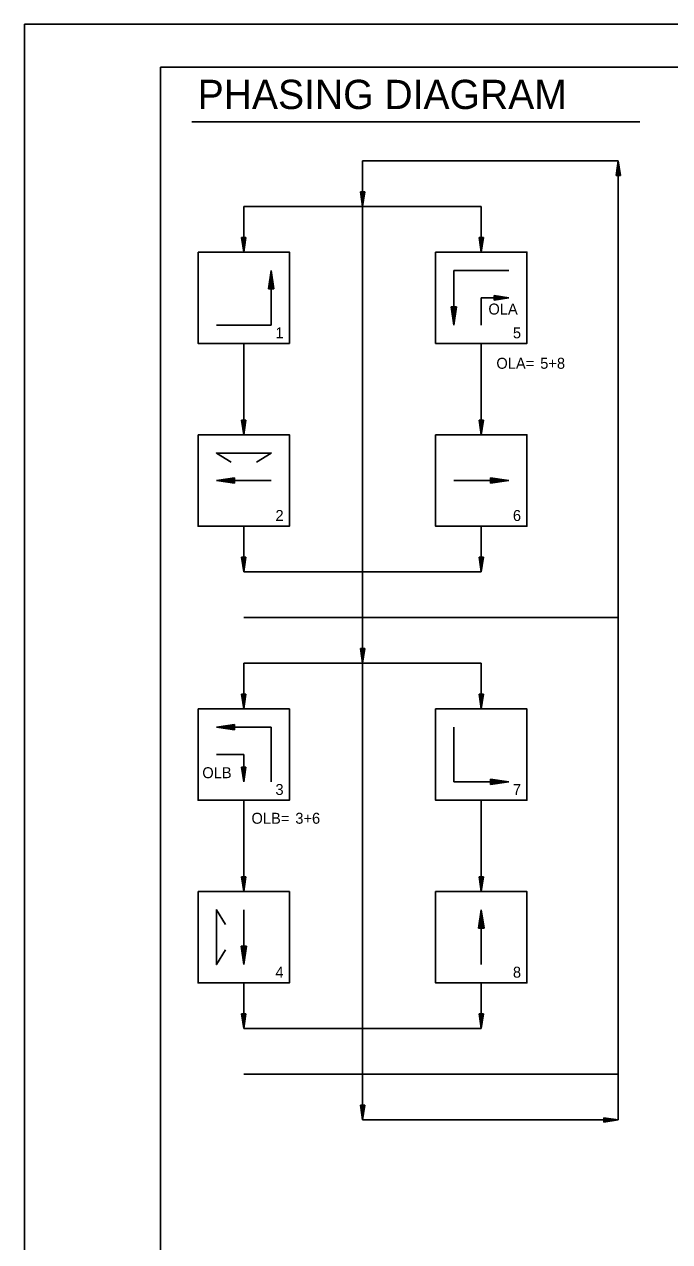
# Model space of a CAD drawing. Extents: x 659404 to 660404, y 642315 to 642955.
# Drawn here: x 659403.7 to 659580.3, y 642622 to 642955.1 of the extents above; entities that cross this region are included whole.
import ezdxf

# ---------------------------------------------------------------- set-up
doc = ezdxf.new("R2010")
doc.units = 0
for name, color, linetype in [('R_Border', 7, 'Continuous'), ('R_Draft', 7, 'Continuous'), ('R_No Plot', 7, 'Continuous'), ('T_Drafting', 7, 'Continuous'), ('T_Notes', 7, 'Continuous')]:
    doc.layers.add(name, color=color, linetype=linetype)

msp = doc.modelspace()

# ---------------------------------------------------------------- linework, layer by layer
at = {"layer": 'R_Border'}
for p, q in [((659440.89, 642943.46), (660389.43, 642943.46)), ((659440.89, 642327.08), (659440.89, 642943.46))]:
    msp.add_line(p, q, dxfattribs=at)
at = {"layer": 'R_Draft'}
for p, q in [((659565.63, 642913.79), (659566.23, 642917.79)), ((659565.73, 642913.79), (659566.23, 642917.12)), ((659565.83, 642913.79), (659566.23, 642916.43)), ((659566.83, 642913.79), (659566.23, 642917.79)), ((659566.73, 642913.79), (659566.23, 642917.12)), ((659566.63, 642913.79), (659566.23, 642916.43)), ((659565.63, 642913.79), (659566.83, 642913.79)), ((659565.93, 642913.79), (659566.23, 642915.76)), ((659566.04, 642913.79), (659566.23, 642915.09)), ((659566.14, 642913.79), (659566.23, 642914.42)), ((659566.53, 642913.79), (659566.23, 642915.76)), ((659566.43, 642913.79), (659566.23, 642915.09)), ((659566.32, 642913.79), (659566.23, 642914.42)), ((659495.63, 642909.29), (659496.23, 642905.29)), ((659496.83, 642909.29), (659495.63, 642909.29)), ((659495.73, 642909.29), (659496.23, 642905.95)), ((659495.83, 642909.29), (659496.23, 642906.64)), ((659495.93, 642909.29), (659496.23, 642907.31)), ((659496.03, 642909.29), (659496.23, 642907.99)), ((659496.14, 642909.29), (659496.23, 642908.65)), ((659496.83, 642909.29), (659496.23, 642905.29)), ((659496.42, 642909.29), (659496.23, 642907.99)), ((659496.63, 642909.29), (659496.23, 642906.64)), ((659496.73, 642909.29), (659496.23, 642905.95)), ((659496.53, 642909.29), (659496.23, 642907.31)), ((659496.32, 642909.29), (659496.23, 642908.65)), ((659463.13, 642896.79), (659463.73, 642892.79)), ((659464.33, 642896.79), (659463.13, 642896.79)), ((659463.23, 642896.79), (659463.73, 642893.45)), ((659463.33, 642896.79), (659463.73, 642894.14)), ((659463.43, 642896.79), (659463.73, 642894.81)), ((659463.53, 642896.79), (659463.73, 642895.49)), ((659463.64, 642896.79), (659463.73, 642896.15)), ((659464.33, 642896.79), (659463.73, 642892.79)), ((659463.92, 642896.79), (659463.73, 642895.49)), ((659464.13, 642896.79), (659463.73, 642894.14)), ((659464.23, 642896.79), (659463.73, 642893.45)), ((659464.03, 642896.79), (659463.73, 642894.81)), ((659463.82, 642896.79), (659463.73, 642896.15)), ((659528.13, 642896.79), (659528.73, 642892.79)), ((659529.33, 642896.79), (659528.13, 642896.79)), ((659528.23, 642896.79), (659528.73, 642893.45)), ((659528.33, 642896.79), (659528.73, 642894.14)), ((659528.43, 642896.79), (659528.73, 642894.81)), ((659528.53, 642896.79), (659528.73, 642895.49)), ((659528.64, 642896.79), (659528.73, 642896.15)), ((659529.33, 642896.79), (659528.73, 642892.79)), ((659528.92, 642896.79), (659528.73, 642895.49)), ((659529.13, 642896.79), (659528.73, 642894.14)), ((659529.23, 642896.79), (659528.73, 642893.45)), ((659529.03, 642896.79), (659528.73, 642894.81)), ((659528.82, 642896.79), (659528.73, 642896.15)), ((659463.13, 642846.79), (659463.73, 642842.79)), ((659464.33, 642846.79), (659463.13, 642846.79)), ((659463.23, 642846.79), (659463.73, 642843.45)), ((659463.33, 642846.79), (659463.73, 642844.14)), ((659463.43, 642846.79), (659463.73, 642844.81)), ((659463.53, 642846.79), (659463.73, 642845.49)), ((659463.64, 642846.79), (659463.73, 642846.15)), ((659464.33, 642846.79), (659463.73, 642842.79)), ((659463.92, 642846.79), (659463.73, 642845.49)), ((659464.13, 642846.79), (659463.73, 642844.14)), ((659464.23, 642846.79), (659463.73, 642843.45)), ((659464.03, 642846.79), (659463.73, 642844.81)), ((659463.82, 642846.79), (659463.73, 642846.15)), ((659528.13, 642846.79), (659528.73, 642842.79)), ((659529.33, 642846.79), (659528.13, 642846.79)), ((659528.23, 642846.79), (659528.73, 642843.45)), ((659528.33, 642846.79), (659528.73, 642844.14)), ((659528.43, 642846.79), (659528.73, 642844.81)), ((659528.53, 642846.79), (659528.73, 642845.49)), ((659528.64, 642846.79), (659528.73, 642846.15)), ((659529.33, 642846.79), (659528.73, 642842.79)), ((659528.92, 642846.79), (659528.73, 642845.49)), ((659529.13, 642846.79), (659528.73, 642844.14)), ((659529.23, 642846.79), (659528.73, 642843.45)), ((659529.03, 642846.79), (659528.73, 642844.81)), ((659528.82, 642846.79), (659528.73, 642846.15)), ((659463.13, 642809.29), (659463.73, 642805.29)), ((659464.33, 642809.29), (659463.13, 642809.29)), ((659463.23, 642809.29), (659463.73, 642805.95)), ((659463.33, 642809.29), (659463.73, 642806.64)), ((659463.43, 642809.29), (659463.73, 642807.31)), ((659463.53, 642809.29), (659463.73, 642807.99)), ((659463.64, 642809.29), (659463.73, 642808.65)), ((659464.33, 642809.29), (659463.73, 642805.29)), ((659463.92, 642809.29), (659463.73, 642807.99)), ((659464.13, 642809.29), (659463.73, 642806.64)), ((659464.23, 642809.29), (659463.73, 642805.95)), ((659464.03, 642809.29), (659463.73, 642807.31)), ((659463.82, 642809.29), (659463.73, 642808.65)), ((659528.13, 642809.29), (659528.73, 642805.29)), ((659529.33, 642809.29), (659528.13, 642809.29)), ((659528.23, 642809.29), (659528.73, 642805.95)), ((659528.33, 642809.29), (659528.73, 642806.64)), ((659528.43, 642809.29), (659528.73, 642807.31)), ((659528.53, 642809.29), (659528.73, 642807.99)), ((659528.64, 642809.29), (659528.73, 642808.65)), ((659529.33, 642809.29), (659528.73, 642805.29)), ((659528.92, 642809.29), (659528.73, 642807.99)), ((659529.13, 642809.29), (659528.73, 642806.64)), ((659529.23, 642809.29), (659528.73, 642805.95)), ((659529.03, 642809.29), (659528.73, 642807.31)), ((659528.82, 642809.29), (659528.73, 642808.65)), ((659495.63, 642784.29), (659496.23, 642780.29)), ((659496.83, 642784.29), (659495.63, 642784.29)), ((659495.73, 642784.29), (659496.23, 642780.95)), ((659495.83, 642784.29), (659496.23, 642781.64)), ((659495.93, 642784.29), (659496.23, 642782.31)), ((659496.03, 642784.29), (659496.23, 642782.99)), ((659496.14, 642784.29), (659496.23, 642783.65)), ((659496.83, 642784.29), (659496.23, 642780.29)), ((659496.42, 642784.29), (659496.23, 642782.99)), ((659496.63, 642784.29), (659496.23, 642781.64)), ((659496.73, 642784.29), (659496.23, 642780.95)), ((659496.53, 642784.29), (659496.23, 642782.31)), ((659496.32, 642784.29), (659496.23, 642783.65)), ((659463.13, 642771.79), (659463.73, 642767.79)), ((659464.33, 642771.79), (659463.13, 642771.79)), ((659463.23, 642771.79), (659463.73, 642768.45)), ((659463.33, 642771.79), (659463.73, 642769.14)), ((659463.43, 642771.79), (659463.73, 642769.81)), ((659463.53, 642771.79), (659463.73, 642770.49)), ((659463.64, 642771.79), (659463.73, 642771.15)), ((659464.33, 642771.79), (659463.73, 642767.79)), ((659463.92, 642771.79), (659463.73, 642770.49)), ((659464.13, 642771.79), (659463.73, 642769.14)), ((659464.23, 642771.79), (659463.73, 642768.45)), ((659464.03, 642771.79), (659463.73, 642769.81)), ((659463.82, 642771.79), (659463.73, 642771.15)), ((659528.13, 642771.79), (659528.73, 642767.79)), ((659529.33, 642771.79), (659528.13, 642771.79)), ((659528.23, 642771.79), (659528.73, 642768.45)), ((659528.33, 642771.79), (659528.73, 642769.14)), ((659528.43, 642771.79), (659528.73, 642769.81)), ((659528.53, 642771.79), (659528.73, 642770.49)), ((659528.64, 642771.79), (659528.73, 642771.15)), ((659529.33, 642771.79), (659528.73, 642767.79)), ((659528.92, 642771.79), (659528.73, 642770.49)), ((659529.13, 642771.79), (659528.73, 642769.14)), ((659529.23, 642771.79), (659528.73, 642768.45)), ((659529.03, 642771.79), (659528.73, 642769.81)), ((659528.82, 642771.79), (659528.73, 642771.15)), ((659463.13, 642721.79), (659463.73, 642717.79)), ((659464.33, 642721.79), (659463.13, 642721.79)), ((659463.23, 642721.79), (659463.73, 642718.45)), ((659463.33, 642721.79), (659463.73, 642719.14)), ((659463.43, 642721.79), (659463.73, 642719.81)), ((659463.53, 642721.79), (659463.73, 642720.49)), ((659463.64, 642721.79), (659463.73, 642721.15)), ((659464.33, 642721.79), (659463.73, 642717.79)), ((659463.92, 642721.79), (659463.73, 642720.49)), ((659464.13, 642721.79), (659463.73, 642719.14)), ((659464.23, 642721.79), (659463.73, 642718.45)), ((659464.03, 642721.79), (659463.73, 642719.81)), ((659463.82, 642721.79), (659463.73, 642721.15)), ((659528.13, 642721.79), (659528.73, 642717.79)), ((659529.33, 642721.79), (659528.13, 642721.79)), ((659528.23, 642721.79), (659528.73, 642718.45)), ((659528.33, 642721.79), (659528.73, 642719.14)), ((659528.43, 642721.79), (659528.73, 642719.81)), ((659528.53, 642721.79), (659528.73, 642720.49)), ((659528.64, 642721.79), (659528.73, 642721.15)), ((659529.33, 642721.79), (659528.73, 642717.79)), ((659528.92, 642721.79), (659528.73, 642720.49)), ((659529.13, 642721.79), (659528.73, 642719.14)), ((659529.23, 642721.79), (659528.73, 642718.45)), ((659529.03, 642721.79), (659528.73, 642719.81)), ((659528.82, 642721.79), (659528.73, 642721.15)), ((659463.13, 642684.29), (659463.73, 642680.29)), ((659464.33, 642684.29), (659463.13, 642684.29)), ((659463.23, 642684.29), (659463.73, 642680.95)), ((659463.33, 642684.29), (659463.73, 642681.64)), ((659463.43, 642684.29), (659463.73, 642682.31)), ((659463.53, 642684.29), (659463.73, 642682.99)), ((659463.64, 642684.29), (659463.73, 642683.65)), ((659464.33, 642684.29), (659463.73, 642680.29)), ((659463.92, 642684.29), (659463.73, 642682.99)), ((659464.13, 642684.29), (659463.73, 642681.64)), ((659464.23, 642684.29), (659463.73, 642680.95)), ((659464.03, 642684.29), (659463.73, 642682.31)), ((659463.82, 642684.29), (659463.73, 642683.65)), ((659528.13, 642684.29), (659528.73, 642680.29)), ((659529.33, 642684.29), (659528.13, 642684.29)), ((659528.23, 642684.29), (659528.73, 642680.95)), ((659528.33, 642684.29), (659528.73, 642681.64)), ((659528.43, 642684.29), (659528.73, 642682.31)), ((659528.53, 642684.29), (659528.73, 642682.99)), ((659528.64, 642684.29), (659528.73, 642683.65)), ((659529.33, 642684.29), (659528.73, 642680.29)), ((659528.92, 642684.29), (659528.73, 642682.99)), ((659529.13, 642684.29), (659528.73, 642681.64)), ((659529.23, 642684.29), (659528.73, 642680.95)), ((659529.03, 642684.29), (659528.73, 642682.31)), ((659528.82, 642684.29), (659528.73, 642683.65)), ((659495.63, 642659.29), (659496.23, 642655.29)), ((659496.83, 642659.29), (659495.63, 642659.29)), ((659495.73, 642659.29), (659496.23, 642655.95)), ((659495.83, 642659.29), (659496.23, 642656.64)), ((659495.93, 642659.29), (659496.23, 642657.31)), ((659496.03, 642659.29), (659496.23, 642657.99)), ((659496.14, 642659.29), (659496.23, 642658.65)), ((659496.83, 642659.29), (659496.23, 642655.29)), ((659496.42, 642659.29), (659496.23, 642657.99)), ((659496.63, 642659.29), (659496.23, 642656.64)), ((659496.73, 642659.29), (659496.23, 642655.95)), ((659496.53, 642659.29), (659496.23, 642657.31)), ((659496.32, 642659.29), (659496.23, 642658.65)), ((659562.23, 642655.89), (659566.23, 642655.29)), ((659562.23, 642655.89), (659562.23, 642654.69)), ((659562.23, 642655.79), (659565.56, 642655.29)), ((659562.23, 642655.68), (659564.87, 642655.29)), ((659562.23, 642655.58), (659564.21, 642655.29)), ((659562.23, 642655.48), (659563.53, 642655.29)), ((659562.23, 642655.38), (659562.86, 642655.29)), ((659562.23, 642654.69), (659566.23, 642655.29)), ((659562.23, 642655.09), (659563.53, 642655.29)), ((659562.23, 642654.89), (659564.87, 642655.29)), ((659562.23, 642654.79), (659565.56, 642655.29)), ((659562.23, 642654.99), (659564.21, 642655.29)), ((659562.23, 642655.19), (659562.86, 642655.29))]:
    msp.add_line(p, q, dxfattribs=at)
at = {"layer": 'R_No Plot'}
msp.add_line((659403.69, 642955.15), (660403.69, 642955.15), dxfattribs=at)
msp.add_lwpolyline([(659403.67, 642955.15), (660403.69, 642955.15), (660403.69, 642315.13), (659403.67, 642315.13)], close=True, dxfattribs=at)
at = {"layer": 'T_Drafting'}
for p, q in [((659496.23, 642655.29), (659496.23, 642917.79)), ((659496.23, 642917.79), (659566.23, 642917.79)), ((659566.23, 642917.79), (659566.23, 642655.29)), ((659463.73, 642892.79), (659463.73, 642905.29)), ((659463.73, 642905.29), (659528.73, 642905.29)), ((659528.73, 642892.79), (659528.73, 642905.29)), ((659470.48, 642882.79), (659471.23, 642887.79)), ((659471.23, 642886.95), (659470.61, 642882.79)), ((659470.73, 642882.79), (659471.23, 642886.09)), ((659471.23, 642872.79), (659471.23, 642887.79)), ((659471.23, 642887.79), (659471.98, 642882.79)), ((659471.86, 642882.79), (659471.23, 642886.95)), ((659471.23, 642886.09), (659471.73, 642882.79)), ((659536.23, 642887.79), (659521.23, 642887.79)), ((659521.23, 642887.79), (659521.23, 642872.79)), ((659470.48, 642882.79), (659471.98, 642882.79)), ((659471.23, 642885.26), (659470.86, 642882.79)), ((659470.99, 642882.79), (659471.23, 642884.41)), ((659471.23, 642883.58), (659471.11, 642882.79)), ((659471.6, 642882.79), (659471.23, 642885.26)), ((659471.23, 642884.41), (659471.48, 642882.79)), ((659471.35, 642882.79), (659471.23, 642883.58)), ((659528.73, 642872.79), (659528.73, 642880.29)), ((659528.73, 642880.29), (659536.23, 642880.29)), ((659536.23, 642880.29), (659532.23, 642880.89)), ((659532.23, 642879.69), (659532.23, 642880.89)), ((659532.23, 642880.79), (659535.56, 642880.29)), ((659534.87, 642880.29), (659532.23, 642880.68)), ((659532.23, 642880.58), (659534.21, 642880.29)), ((659533.53, 642880.29), (659532.23, 642880.48)), ((659532.23, 642880.38), (659532.86, 642880.29)), ((659532.86, 642880.29), (659532.23, 642880.19)), ((659532.23, 642880.09), (659533.53, 642880.29)), ((659534.21, 642880.29), (659532.23, 642879.99)), ((659532.23, 642879.89), (659534.87, 642880.29)), ((659535.56, 642880.29), (659532.23, 642879.79)), ((659532.23, 642879.69), (659536.23, 642880.29)), ((659521.23, 642872.79), (659520.48, 642877.79)), ((659521.98, 642877.79), (659520.48, 642877.79)), ((659520.61, 642877.79), (659521.23, 642873.62)), ((659521.23, 642874.48), (659520.73, 642877.79)), ((659520.86, 642877.79), (659521.23, 642875.31)), ((659521.23, 642876.16), (659520.99, 642877.79)), ((659521.11, 642877.79), (659521.23, 642877)), ((659521.23, 642877), (659521.35, 642877.79)), ((659521.47, 642877.79), (659521.23, 642876.16)), ((659521.23, 642875.31), (659521.6, 642877.79)), ((659521.73, 642877.79), (659521.23, 642874.48)), ((659521.23, 642873.62), (659521.86, 642877.79)), ((659521.98, 642877.79), (659521.23, 642872.79)), ((659456.23, 642872.79), (659471.23, 642872.79)), ((659463.73, 642842.79), (659463.73, 642867.79)), ((659528.73, 642842.79), (659528.73, 642867.79)), ((659456.23, 642830.29), (659461.23, 642831.04)), ((659471.23, 642830.29), (659456.23, 642830.29)), ((659461.23, 642829.54), (659456.23, 642830.29)), ((659461.23, 642830.91), (659457.07, 642830.29)), ((659457.07, 642830.29), (659461.23, 642829.66)), ((659457.93, 642830.29), (659461.23, 642830.78)), ((659461.23, 642829.79), (659457.93, 642830.29)), ((659461.23, 642830.66), (659458.76, 642830.29)), ((659458.76, 642830.29), (659461.23, 642829.91)), ((659459.61, 642830.29), (659461.23, 642830.53)), ((659461.23, 642830.04), (659459.61, 642830.29)), ((659461.23, 642830.4), (659460.44, 642830.29)), ((659460.44, 642830.29), (659461.23, 642830.17)), ((659461.23, 642829.54), (659461.23, 642831.04)), ((659521.23, 642830.29), (659536.23, 642830.29)), ((659531.23, 642831.04), (659536.23, 642830.29)), ((659531.23, 642831.04), (659531.23, 642829.54)), ((659535.4, 642830.29), (659531.23, 642830.91)), ((659531.23, 642830.78), (659534.54, 642830.29)), ((659533.7, 642830.29), (659531.23, 642830.66)), ((659531.23, 642830.53), (659532.86, 642830.29)), ((659532.02, 642830.29), (659531.23, 642830.4)), ((659536.23, 642830.29), (659531.23, 642829.54)), ((659531.23, 642829.66), (659535.4, 642830.29)), ((659534.54, 642830.29), (659531.23, 642829.79)), ((659531.23, 642829.91), (659533.7, 642830.29)), ((659532.86, 642830.29), (659531.23, 642830.04)), ((659531.23, 642830.17), (659532.02, 642830.29)), ((659463.73, 642805.29), (659463.73, 642817.79)), ((659528.73, 642805.29), (659528.73, 642817.79)), ((659463.73, 642805.29), (659528.73, 642805.29)), ((659463.73, 642792.79), (659566.23, 642792.79)), ((659463.73, 642780.29), (659528.73, 642780.29)), ((659463.73, 642767.79), (659463.73, 642780.29)), ((659528.73, 642767.79), (659528.73, 642780.29)), ((659456.23, 642762.79), (659461.23, 642763.54)), ((659471.23, 642762.79), (659456.23, 642762.79)), ((659461.23, 642762.04), (659456.23, 642762.79)), ((659461.23, 642763.41), (659457.07, 642762.79)), ((659457.07, 642762.79), (659461.23, 642762.16)), ((659457.93, 642762.79), (659461.23, 642763.28)), ((659461.23, 642762.29), (659457.93, 642762.79)), ((659461.23, 642763.16), (659458.76, 642762.79)), ((659458.76, 642762.79), (659461.23, 642762.41)), ((659459.61, 642762.79), (659461.23, 642763.03)), ((659461.23, 642762.54), (659459.61, 642762.79)), ((659461.23, 642762.9), (659460.44, 642762.79)), ((659460.44, 642762.79), (659461.23, 642762.67)), ((659461.23, 642762.04), (659461.23, 642763.54)), ((659471.23, 642747.79), (659471.23, 642762.79)), ((659521.23, 642762.79), (659521.23, 642747.79)), ((659456.23, 642755.29), (659463.73, 642755.29)), ((659463.73, 642755.29), (659463.73, 642747.79)), ((659463.13, 642751.79), (659463.73, 642747.79)), ((659463.13, 642751.79), (659464.33, 642751.79)), ((659463.73, 642748.45), (659463.23, 642751.79)), ((659463.33, 642751.79), (659463.73, 642749.14)), ((659463.73, 642749.81), (659463.43, 642751.79)), ((659463.54, 642751.79), (659463.73, 642750.49)), ((659463.73, 642751.15), (659463.64, 642751.79)), ((659463.73, 642747.79), (659464.33, 642751.79)), ((659464.23, 642751.79), (659463.73, 642748.45)), ((659463.73, 642749.14), (659464.13, 642751.79)), ((659464.03, 642751.79), (659463.73, 642749.81)), ((659463.73, 642750.49), (659463.93, 642751.79)), ((659463.82, 642751.79), (659463.73, 642751.15)), ((659521.23, 642747.79), (659536.23, 642747.79)), ((659531.23, 642748.54), (659536.23, 642747.79)), ((659531.23, 642748.54), (659531.23, 642747.04)), ((659535.4, 642747.79), (659531.23, 642748.41)), ((659531.23, 642748.28), (659534.54, 642747.79)), ((659533.7, 642747.79), (659531.23, 642748.16)), ((659531.23, 642748.03), (659532.86, 642747.79)), ((659532.02, 642747.79), (659531.23, 642747.9)), ((659536.23, 642747.79), (659531.23, 642747.04)), ((659531.23, 642747.16), (659535.4, 642747.79)), ((659534.54, 642747.79), (659531.23, 642747.29)), ((659531.23, 642747.41), (659533.7, 642747.79)), ((659532.86, 642747.79), (659531.23, 642747.54)), ((659531.23, 642747.67), (659532.02, 642747.79)), ((659463.73, 642717.79), (659463.73, 642742.79)), ((659528.73, 642717.79), (659528.73, 642742.79)), ((659463.73, 642712.79), (659463.73, 642697.79)), ((659527.98, 642707.79), (659528.73, 642712.79)), ((659528.73, 642697.79), (659528.73, 642712.79)), ((659528.73, 642712.79), (659529.48, 642707.79)), ((659528.73, 642711.95), (659528.11, 642707.79)), ((659528.23, 642707.79), (659528.73, 642711.09)), ((659528.73, 642710.26), (659528.36, 642707.79)), ((659529.36, 642707.79), (659528.73, 642711.95)), ((659528.73, 642711.09), (659529.23, 642707.79)), ((659529.1, 642707.79), (659528.73, 642710.26)), ((659527.98, 642707.79), (659529.48, 642707.79)), ((659528.49, 642707.79), (659528.73, 642709.41)), ((659528.73, 642708.58), (659528.61, 642707.79)), ((659528.73, 642709.41), (659528.98, 642707.79)), ((659528.85, 642707.79), (659528.73, 642708.58)), ((659463.73, 642697.79), (659462.98, 642702.79)), ((659464.48, 642702.79), (659462.98, 642702.79)), ((659463.11, 642702.79), (659463.73, 642698.62)), ((659463.73, 642699.48), (659463.23, 642702.79)), ((659463.36, 642702.79), (659463.73, 642700.31)), ((659463.73, 642701.16), (659463.49, 642702.79)), ((659463.61, 642702.79), (659463.73, 642702)), ((659463.73, 642702), (659463.85, 642702.79)), ((659463.97, 642702.79), (659463.73, 642701.16)), ((659463.73, 642700.31), (659464.1, 642702.79)), ((659464.23, 642702.79), (659463.73, 642699.48)), ((659463.73, 642698.62), (659464.36, 642702.79)), ((659464.48, 642702.79), (659463.73, 642697.79)), ((659463.73, 642680.29), (659463.73, 642692.79)), ((659528.73, 642680.29), (659528.73, 642692.79)), ((659463.73, 642680.29), (659528.73, 642680.29)), ((659463.73, 642667.79), (659566.23, 642667.79)), ((659496.23, 642655.29), (659566.23, 642655.29))]:
    msp.add_line(p, q, dxfattribs=at)
for points in [[(659451.23, 642892.79), (659476.23, 642892.79), (659476.23, 642867.79), (659451.23, 642867.79)], [(659516.23, 642892.79), (659541.23, 642892.79), (659541.23, 642867.79), (659516.23, 642867.79)], [(659451.23, 642842.79), (659476.23, 642842.79), (659476.23, 642817.79), (659451.23, 642817.79)], [(659516.23, 642842.79), (659541.23, 642842.79), (659541.23, 642817.79), (659516.23, 642817.79)], [(659451.23, 642767.79), (659476.23, 642767.79), (659476.23, 642742.79), (659451.23, 642742.79)], [(659516.23, 642767.79), (659541.23, 642767.79), (659541.23, 642742.79), (659516.23, 642742.79)], [(659451.23, 642717.79), (659476.23, 642717.79), (659476.23, 642692.79), (659451.23, 642692.79)], [(659516.23, 642717.79), (659541.23, 642717.79), (659541.23, 642692.79), (659516.23, 642692.79)]]:
    msp.add_lwpolyline(points, close=True, dxfattribs=at)
for points in [[(659460.23, 642835.29), (659456.23, 642837.79), (659471.23, 642837.79), (659467.23, 642835.29)], [(659458.73, 642701.79), (659456.23, 642697.79), (659456.23, 642712.79), (659458.73, 642708.79)]]:
    msp.add_lwpolyline(points, dxfattribs=at)
at = {"layer": 'T_Notes'}
msp.add_line((659449.5, 642928.5), (659572.15, 642928.5), dxfattribs=at)

# ---------------------------------------------------------------- texts
at = {"layer": 'T_Drafting'}
for s, p in [('OLA', (659530.68, 642875.72)), ('OLA=', (659532.86, 642860.87)), ('5+8', (659544.86, 642860.87)), ('OLB', (659452.37, 642748.81)), ('OLB=', (659465.83, 642736.34)), ('3+6', (659477.83, 642736.34))]:
    msp.add_text(s, height=3, dxfattribs=at).set_placement(p)
at = {"layer": 'T_Notes'}
for s, height, p in [('PHASING DIAGRAM', 8, (659451.1, 642931.97)), ('1', 3, (659472.39, 642869.21)), ('5', 3, (659537.39, 642869.21)), ('2', 3, (659472.39, 642819.21)), ('6', 3, (659537.39, 642819.21)), ('3', 3, (659472.39, 642744.21)), ('7', 3, (659537.39, 642744.21)), ('4', 3, (659472.39, 642694.21)), ('8', 3, (659537.39, 642694.21))]:
    msp.add_text(s, height=height, dxfattribs=at).set_placement(p)

doc.saveas('drawing.dxf')
